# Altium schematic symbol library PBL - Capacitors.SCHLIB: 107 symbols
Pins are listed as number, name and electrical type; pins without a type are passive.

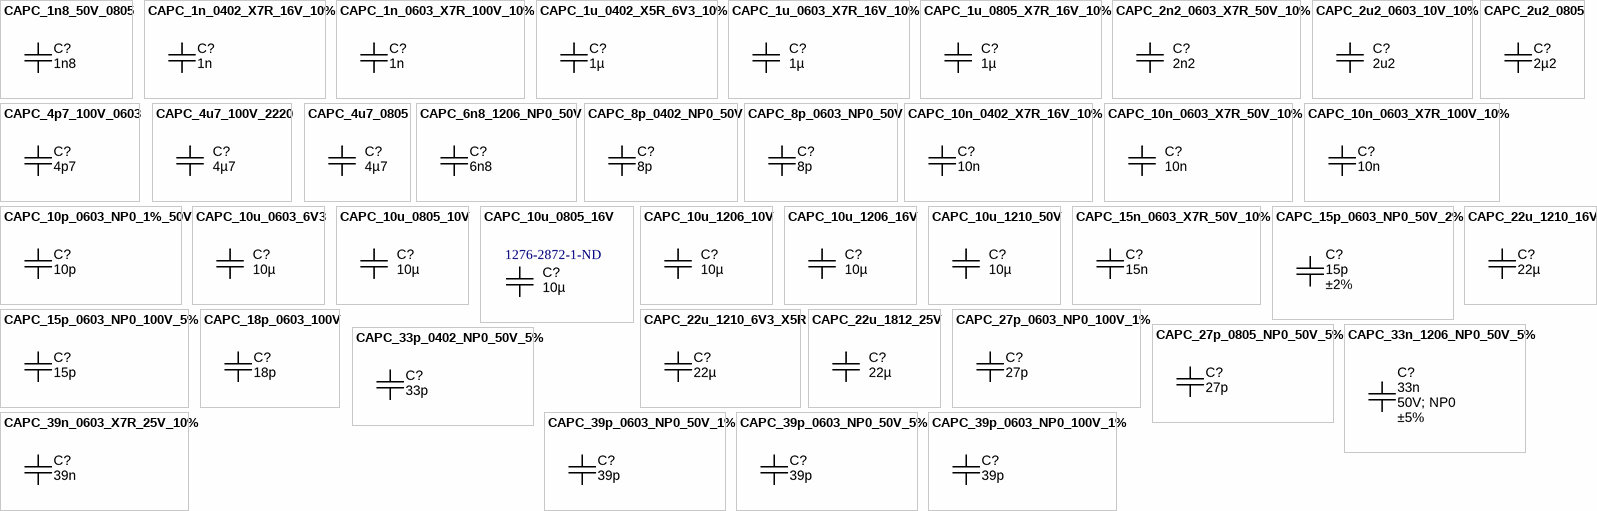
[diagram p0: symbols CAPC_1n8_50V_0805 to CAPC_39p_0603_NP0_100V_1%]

## CAPC_1n8_50V_0805
designator C?, comment value 1n8  (hidden comment: approved sub OK)
Capacitor SMD Cer 1.8nF 10% 50V X7R 0805; Manufacturer 1: AVX Corporation; Manufacturer Part Number 1: 08055C182KAT2A; Ratings: 50V; X7R; SCDType: source*
footprint CAPC2012X135N (Chip Capacitor, Body 2.0x1.2mm, 0805, IPC Medium Density)
pins: 1, 2

## CAPC_1n_0402_X7R_16V_10%
designator C?, comment 1n
Capacitor SMD Cer 1nF 10% 16V X7R 0402; Manufacturer 1: AVX Corporation; Manufacturer Part Number 1: 0402YC102KAT2A; Ratings: 16V; X7R; SCDType: spec
footprint CAPC1005X55N (Chip Capacitor, Body 1.0x0.5mm, 0402, IPC Medium Density)
pins: 1, 2

## CAPC_1n_0603_X7R_100V_10%
designator C?, comment value 1n  (hidden comment: approved sub OK)
Capacitor SMD Cer 1nF 10% 100V X7R 0603; Manufacturer 1: Murata Electronics North America; Manufacturer Part Number 1: GCM188R72A102KA37D; Ratings: 100V; X7R; Material: ceramic; SCDType: spec
footprint CAPC1608X90N (Chip Capacitor, Body 1.6x0.8mm, 0603, IPC Medium Density)
pins: 1, 2

## CAPC_1u_0402_X5R_6V3_10%
designator C?, comment 1µ
Capacitor SMD Cer 1uF 10% 16V X5R 0402; Manufacturer 1: AVX Corporation; Manufacturer Part Number 1: 04026D105KAT2A; Ratings: 6.3V; X5R; SCDType: spec
footprint CAPC1005X55N (Chip Capacitor, Body 1.0x0.5mm, 0402, IPC Medium Density)
pins: 1, 2

## CAPC_1u_0603_X7R_16V_10%
designator C?, comment value 1µ  (hidden comment: approved sub OK)
Capacitor SMD Cer 1uF 10% 16V X7R 0603; Manufacturer 1: TDK Corporation; Manufacturer Part Number 1: C1608X7R1C105K; Ratings: 16V; X7R; Material: ceramic; SCDType: spec
footprint CAPC1608X90N (Chip Capacitor, Body 1.6x0.8mm, 0603, IPC Medium Density)
pins: 1, 2

## CAPC_1u_0805_X7R_16V_10%
designator C?, comment value 1µ  (hidden comment: approved sub OK)
Capacitor SMD Cer 1uF 10% 16V X7R 0805; Manufacturer 1: Yageo; Manufacturer Part Number 1: CC0805KKX7R7BB105; Ratings: 16V; X7R; Material: ceramic; SCDType: spec
footprint CAPC2012X135N (Chip Capacitor, Body 2.0x1.2mm, 0805, IPC Medium Density)
pins: 1, 2

## CAPC_2n2_0603_X7R_50V_10%
designator C?, comment value 2n2  (hidden comment: approved sub OK)
Capacitor SMD Cer 2n2F 10% 50V X7R 0603
footprint CAPC1608X90N (Chip Capacitor, Body 1.6x0.8mm, 0603, IPC Medium Density)
pins: 1, 2

## CAPC_2u2_0603_10V_10%
designator C?, comment value 2u2  (hidden comment: approved sub OK)
Capacitor SMD Cer 2.2uF 10% 10V X5R 0603; Manufacturer 1: AVX Corporation; Manufacturer Part Number 1: 0603ZD225KAT2A; Ratings: 10V; X5R; Material: ceramic; SCDType: spec
footprint CAPC1608X90N (Chip Capacitor, Body 1.6x0.8mm, 0603, IPC Medium Density)
pins: 1, 2

## CAPC_2u2_0805
designator C?, comment value 2µ2  (hidden comment: approved sub OK)
Capacitor SMD Cer 2.2uF 10% 16V X7R 0805; Manufacturer 1: Kemet; Manufacturer Part Number 1: C0805C225K4RACTU; Ratings: 16V; X7R; SCDType: undef
footprint CAPC2012X135N (Chip Capacitor, Body 2.0x1.2mm, 0805, IPC Medium Density)
pins: 1, 2

## CAPC_4p7_100V_0603
designator C?, comment value 4p7  (hidden comment: approved sub OK)
Capacitor SMD Cer 4.7pF ±0.25pF 100V NP0 0603; Manufacturer 1: AVX Corporation; Manufacturer Part Number 1: 06031A4R7CAT2A; Ratings: 100V; NP0; SCDType: source*
footprint CAPC1608X90N (Chip Capacitor, Body 1.6x0.8mm, 0603, IPC Medium Density)
pins: 1, 2

## CAPC_4u7_100V_2220
designator C?, comment value 4µ7  (hidden comment: approved sub OK)
Capacitor SMD Cer 4.7uF 10% 100V X7R 2220; Manufacturer: TDK Corporation; Manufacturer Part Number: C5750X7R2A475K; Ratings: 100V; X7R; Material: ceramic; SCDType: undef
footprint CAPC5750X250N (Chip Capacitor, Body 5.7x5.0mm, 2220, IPC Medium Density)
pins: 1, 2

## CAPC_4u7_0805
designator C?, comment value 4µ7  (hidden comment: approved sub OK)
Capacitor SMD Cer 4.7uF 10% 16V X5R 0805; Manufacturer 1: Taiyo Yuden; Manufacturer Part Number 1: EMK212BJ475KG-T; Ratings: 16V; X5R; Material: ceramic; SCDType: spec
footprint CAPC2012X135N (Chip Capacitor, Body 2.0x1.2mm, 0805, IPC Medium Density)
pins: 1, 2

## CAPC_6n8_1206_NP0_50V
designator C?, comment 6n8
Capacitor SMD Cer 6.8nF 5% 50V NP0 1206; Manufacturer 1: TDK Corporation; Manufacturer Part Number 1: C3216C0G1H682J/0.60; Ratings: 50V; NP0; Material: Ceramic NP0; SCDType: spec
footprint CAPC3216X180N (Chip Capacitor, Body 3.2x1.6mm, 1.8mm H, 1206, IPC Medium Density)
pins: 1, 2

## CAPC_8p_0402_NP0_50V
designator C?, comment 8p
Capacitor SMD Cer 8pF ±0.5pF 50V NP0 0402; Manufacturer 1: Murata Electronics North America; Manufacturer Part Number 1: GRM1555C1H8R0DA01D; Ratings: 50V; NP0; SCDType: spec
footprint CAPC1005X55N (Chip Capacitor, Body 1.0x0.5mm, 0402, IPC Medium Density)
pins: 1, 2

## CAPC_8p_0603_NP0_50V
designator C?, comment 8p
Capacitor SMD Cer 8pF ±0.5pF 50V NP0 0603; Manufacturer 1: Murata Electronics North America; Manufacturer Part Number 1: GRM1885C1H8R0DZ01D; Ratings: 50V; NP0; SCDType: undef
footprint CAPC1608X90N (Chip Capacitor, Body 1.6x0.8mm, 0603, IPC Medium Density)
pins: 1, 2

## CAPC_10n_0402_X7R_16V_10%
designator C?, comment 10n
Capacitor SMD Cer 10nF 10% 16V X7R 0402; Manufacturer 1: AVX Corporation; Manufacturer Part Number 1: 0402YC103KAT2A; Ratings: 16V; X7R; SCDType: spec
footprint CAPC1005X55N (Chip Capacitor, Body 1.0x0.5mm, 0402, IPC Medium Density)
pins: 1, 2

## CAPC_10n_0603_X7R_50V_10%
designator C?, comment value 10n  (hidden comment: approved sub OK)
Capacitor SMD Cer 10nF 10% 50V X7R 0603; Manufacturer 1: TDK Corporation; Manufacturer Part Number 1: C1608X7R1H103K; Ratings: 50V; X7R; Material: ceramic; SCDType: spec
footprint CAPC1608X90N (Chip Capacitor, Body 1.6x0.8mm, 0603, IPC Medium Density)
pins: 1, 2

## CAPC_10n_0603_X7R_100V_10%
designator C?, comment value 10n  (hidden comment: approved sub OK)
Capacitor SMD Cer 10nF 10% 100V X7R 0603; Manufacturer: Murata Electronics North America; Manufacturer Part Number: GCM188R72A103KA37D; Ratings: 100V; X7R; Material: ceramic; SCDType: undef
footprint CAPC1608X90N (Chip Capacitor, Body 1.6x0.8mm, 0603, IPC Medium Density)
pins: 1, 2

## CAPC_10p_0603_NP0_1%_50V
designator C?, comment 10p
Capacitor SMD Cer 10pF 5% 50V NP0 0603; Manufacturer 1: Murata Electronics North America; Manufacturer Part Number 1: GRM1885C1H100FA01J; Ratings: 50V; NP0; SCDType: spec
footprint CAPC1608X90N (Chip Capacitor, Body 1.6x0.8mm, 0603, IPC Medium Density)
pins: 1, 2

## CAPC_10u_0603_6V3
designator C?, comment value 10µ  (hidden comment: approved sub OK)
Capacitor SMD Cer 10uF 10% 10V X5R 0603; Ratings: 10V; X5R; Material: ceramic; SCDType: spec
footprint CAPC1608X90N (Chip Capacitor, Body 1.6x0.8mm, EIA 0603, IPC Medium Density)
pins: 1, 2

## CAPC_10u_0805_10V
designator C?, comment value 10µ  (hidden comment: approved sub OK)
Capacitor SMD Cer 10uF 10% 10V X5R 0805; Manufacturer 1: AVX Corporation; Manufacturer Part Number 1: 0805ZD106KAT2A; Ratings: 10V; X5R; Material: ceramic; SCDType: spec
footprint CAPC2012X135N (Chip Capacitor, Body 2.0x1.2mm, 0805, IPC Medium Density)
pins: 1, 2

## CAPC_10u_0805_16V
designator C?, comment value 10µ  Supplier Part Number 1: 1276-2872-1-ND  (hidden comment: approved sub OK)
Capacitor SMD Cer 10uF 10% 16V X7R 0805; Manufacturer 1: Samsung; Manufacturer Part Number 1: CL21B106KOQNNNE; Ratings: 16V; X7R; Material: ceramic; SCDType: undef
footprint CAPC1608N (Chip Capacitor, Body 1.6x0.8mm, IPC Medium Density)
footprint CAPC3216N (Chip Capacitor, Body 3.2x1.6mm, IPC Medium Density)
footprint CAPC2012X135N (Chip Capacitor, Body 2.0x1.2mm, 0805, IPC Medium Density)
pins: 1, 2

## CAPC_10u_1206_10V
designator C?, comment value 10µ  (hidden comment: approved sub OK)
Capacitor SMD Cer 10uF 10% 10V X5R 1206; Manufacturer 1: KEMET; Manufacturer Part Number 1: C1206C106K8PACTU; Ratings: 10V; X5R; Material: ceramic; SCDType: undef
footprint CAPC3216X180N (Chip Capacitor, Body 3.2x1.6mm, 1.8mm H, 1206, IPC Medium Density)
pins: 1, 2

## CAPC_10u_1206_16V
designator C?, comment value 10µ  (hidden comment: approved sub OK)
Capacitor SMD Cer 10uF 10% 16V X7R 1206; Manufacturer 1: Kemet; Manufacturer Part Number 1: C1206C106K4RACTU; Ratings: 16V; X7R; Material: ceramic; SCDType: spec
footprint CAPC3216X180N (Chip Capacitor, Body 3.2x1.6mm, 1.8mm H, 1206, IPC Medium Density)
pins: 1, 2

## CAPC_10u_1210_50V
designator C?, comment 10µ
Capacitor SMD Cer 10uF 20% 16V X5R 1210; Manufacturer 1: Taiyo Yuden; Manufacturer Part Number 1: UMK325BJ106MM-T; Ratings: 50V; X5R; Material: ceramic; SCDType: spec
footprint CAPC3225X220N (Chip Capacitor, Body 3.2x2.5mm, 1210, IPC Medium Density)
pins: 1, 2

## CAPC_15n_0603_X7R_50V_10%
designator C?, comment value 15n  (hidden comment: approved sub OK)
Capacitor SMD Cer 15nF 10% 50V X7R 0603; Manufacturer Part Number 1: GRM188R71H153KA01D; Manufacturer 1: Murata Electronics North America; Ratings: 50V; X7R; SCDType: spec
footprint CAPC1608X90N (Chip Capacitor, Body 1.6x0.8mm, 0603, IPC Medium Density)
pins: 1, 2

## CAPC_15p_0603_NP0_50V_2%
designator C?, comment Tolerance: ±2%  (hidden comment: 15p)
Capacitor SMD Cer 15pF 2% 50V NP0 0603; Manufacturer 1: TDK Corporation; Manufacturer Part Number 1: C1608C0G1H150G080AA; Ratings: 50V; NP0; SCDType: source
pins: 1, 2

## CAPC_15p_0603_NP0_100V_5%
designator C?, comment 15p
Capacitor SMD Cer 15pF 5% 100V NP0 0603; Manufacturer 1: AVX Corporation; Manufacturer Part Number 1: 06031A150JAT2A; Ratings: 100V; NP0; SCDType: spec
footprint CAPC1608X90N (Chip Capacitor, Body 1.6x0.8mm, 0603, IPC Medium Density)
pins: 1, 2

## CAPC_18p_0603_100V
designator C?, comment 18p
Capacitor SMD Cer 18pF 2% 100V NP0 0603; Manufacturer 1: AVX Corporation; Manufacturer Part Number 1: 06031A180GAT2A; Ratings: 100V; NP0; SCDType: spec
footprint CAPC1608X90N (Chip Capacitor, Body 1.6x0.8mm, 0603, IPC Medium Density)
pins: 1, 2

## CAPC_22u_1210_6V3_X5R
designator C?, comment value 22µ  (hidden comment: approved sub OK)
Capacitor SMD Cer 22uF 20% 6.3V X5R 1210; Manufacturer 1: TDK Corporation; Manufacturer Part Number 1: C3225X5R0J226M/2.00; Ratings: 6.3V; X5R; Voltage - Rated: 6V3; SCDType: spec
footprint CAPC3225X220N (Chip Capacitor, Body 3.2x2.5mm, 1210, IPC Medium Density)
pins: 1, 2

## CAPC_22u_1210_16V
designator C?, comment value 22µ  (hidden comment: approved sub OK)
Capacitor SMD Cer 22uF 20% 16V X7R 1210; Manufacturer: TDK Corporation; Manufacturer Part Number: C3225X7R1C226K; Ratings: 16V; X7R; SCDType: spec
footprint CAPC3225X220N (Chip Capacitor, Body 3.2x2.5mm, 1210, IPC Medium Density)
pins: 1, 2

## CAPC_22u_1812_25V
designator C?, comment value 22µ  (hidden comment: approved sub OK)
Capacitor SMD Cer 22uF 20% 25V X5R 1812; Manufacturer 1: TDK Corporation; Manufacturer Part Number 1: C4532X5R1E226M; Ratings: 25V; X5R; Material: ceramic; SCDType: undef
footprint CAPC4532X280N (Chip Capacitor, Body 4.5x3.2mm, 1812, IPC Medium Density)
pins: 1, 2

## CAPC_27p_0603_NP0_100V_1%
designator C?, comment 27p
Capacitor SMD Cer 27pF 1% 100V NP0 0603; Manufacturer 1: AVX Corporation; Manufacturer Part Number 1: 06031A270FAT2A; Ratings: 100V; NP0; SCDType: undef
footprint CAPC1608X90N (Chip Capacitor, Body 1.6x0.8mm, 0603, IPC Medium Density)
pins: 1, 2

## CAPC_27p_0805_NP0_50V_5%
designator C?, comment value 27p  (hidden comment: approved sub OK)
Capacitor SMD Cer 27pF 5% 50V NP0 0805; Manufacturer 1: Panasonic - ECG; Manufacturer Part Number 1: ECJ-2VC1H270J; Ratings: 50V; NP0; SCDType: undef
footprint CAPC2012X135N (Chip Capacitor, Body 2.0x1.2mm, 0805, IPC Medium Density)
pins: 1, 2

## CAPC_33n_1206_NP0_50V_5%
designator C?, comment Tolerance: ±5%  Ratings: 50V; NP0  (hidden comment: 33n)
Capacitor SMD Cer 33nF 1206 NP0 50V 5%; Manufacturer 1: TDK Corporation; Manufacturer Part Number 1: C3216C0G1H333J085AA; SCDType: undef
footprint CAPC3216X100N (Chip Capacitor, Body 3.2x1.6mm, 1.0mm H, 1206, IPC Medium Density)
pins: 1, 2

## CAPC_33p_0402_NP0_50V_5%
designator C?, comment 33p
Capacitor SMD Cer 33pF 5% 50V NP0 0402; Manufacturer 1: AVX Corporation; Manufacturer Part Number 1: 04025A330JAT2A; Ratings: 50V; NP0; SCDType: spec
footprint CAPC1005X55N (Chip Capacitor, Body 1.0x0.5mm, 0402, IPC Medium Density)
pins: 1, 2

## CAPC_39n_0603_X7R_25V_10%
designator C?, comment value 39n  (hidden comment: approved sub OK)
Capacitor SMD Cer 39nF 10% 25V X7R 0603; Manufacturer 1: Kemet; Manufacturer Part Number 1: C0603C393K3RACTU; Ratings: 100V; X7R; Material: ceramic; SCDType: spec
footprint CAPC1608X90N (Chip Capacitor, Body 1.6x0.8mm, 0603, IPC Medium Density)
pins: 1, 2

## CAPC_39p_0603_NP0_50V_1%
designator C?, comment 39p
Capacitor SMD Cer 39pF 1% 50V NP0 0603; Manufacturer 1: AVX Corporation; Manufacturer Part Number 1: 06035A390FAT; Ratings: 50V; NP0; SCDType: source; Temperature Coefficient: C0G, NP0
footprint CAPC1608X90N (Chip Capacitor, Body 1.6x0.8mm, 0603, IPC Medium Density)
pins: 1, 2

## CAPC_39p_0603_NP0_50V_5%
designator C?, comment 39p
Capacitor SMD Cer 39pF 5% 50V NP0 0603; Manufacturer 1: TDK Corporation; Manufacturer Part Number 1: C1608C0G1H390J; Ratings: 50V; NP0; SCDType: undef
footprint CAPC1608X90N (Chip Capacitor, Body 1.6x0.8mm, 0603, IPC Medium Density)
pins: 1, 2

## CAPC_39p_0603_NP0_100V_1%
designator C?, comment 39p
Capacitor SMD Cer 39pF 1% 100V NP0 0603; Manufacturer 1: AVX Corporation; Manufacturer Part Number 1: 06031A390FAT2A; Ratings: 100V; NP0; SCDType: source; Temperature Coefficient: C0G, NP0
footprint CAPC1608X90N (Chip Capacitor, Body 1.6x0.8mm, 0603, IPC Medium Density)
pins: 1, 2

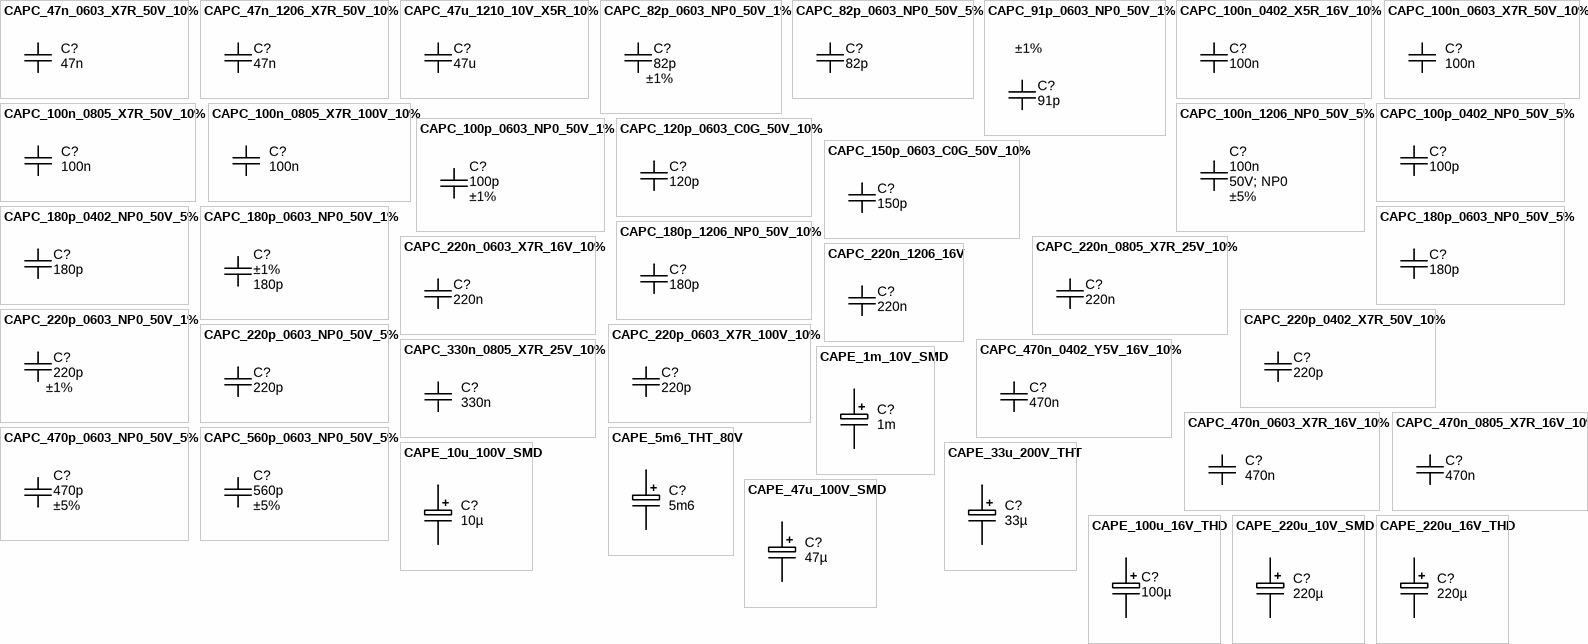
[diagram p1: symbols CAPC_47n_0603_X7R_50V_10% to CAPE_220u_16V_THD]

## CAPC_47n_0603_X7R_50V_10%
designator C?, comment 47n
Capacitor SMD Cer 47nF 10% 50V X7R 0603; Manufacturer 1: AVX Corporation; Manufacturer Part Number 1: 06035C473KAT2A; Ratings: 50V; X7R; Material: ceramic; SCDType: spec
footprint CAPC1608X90N (Chip Capacitor, Body 1.6x0.8mm, 0603, IPC Medium Density)
footprint CAPC3216N (Chip Capacitor, Body 3.2x1.6mm, IPC Medium Density)
footprint CAPC2012N (Chip Capacitor, Body 2.0x1.2mm, IPC Medium Density)
pins: 1, 2

## CAPC_47n_1206_X7R_50V_10%
designator C?, comment 47n
Capacitor SMD Cer 47nF 10% 50V X7R 1206; Manufacturer 1: Yageo; Manufacturer Part Number 1: CC1206KRX7R9BB473; Ratings: 50V; X7R; SCDType: spec
footprint CAPC3216X180N (Chip Capacitor, Body 3.2x1.6mm, 1.8mm H, 1206, IPC Medium Density)
pins: 1, 2

## CAPC_47u_1210_10V_X5R_10%
designator C?, comment 47u
Capacitor SMD Cer 47uF 10% 10V 1210; Manufacturer 1: Murata Electronics North America; Manufacturer Part Number 1: GRM32ER61A476KE20L; Ratings: 10V; X5R; SCDType: undef
footprint CAPC3225X220N (Chip Capacitor, Body 3.2x2.5mm, 1210, IPC Medium Density)
pins: 1, 2

## CAPC_82p_0603_NP0_50V_1%
designator C?, comment Tolerance: ±1%  (hidden comment: 82p)
Capacitor SMD Cer 82pF 1% 50V NP0 0603; Manufacturer 1: Kemet; Manufacturer Part Number 1: C0603C820F5GACTU; Ratings: 50V; NP0; SCDType: spec
footprint CAPC1608X90N (Chip Capacitor, Body 1.6x0.8mm, 0603, IPC Medium Density)
pins: 1, 2

## CAPC_82p_0603_NP0_50V_5%
designator C?, comment 82p
Capacitor SMD Cer 82pF 5% 50V NP0 0603; Manufacturer 1: Yageo; Manufacturer Part Number 1: CC0603JRNPO9BN820; Ratings: 50V; NP0; SCDType: undef
footprint CAPC1608X90N (Chip Capacitor, Body 1.6x0.8mm, 0603, IPC Medium Density)
pins: 1, 2

## CAPC_91p_0603_NP0_50V_1%
designator C?, comment Tolerance: ±1%  (hidden comment: 91p)
Capacitor SMD Cer 91pF 1% 50V NP0 0603; Manufacturer 1: AVX Corporation; Manufacturer Part Number 1: 06035U910FAT2A; Ratings: 50V; NP0; SCDType: source
footprint CAPC1608X90N (Chip Capacitor, Body 1.6x0.8mm, 0603, IPC Medium Density)
pins: 1, 2

## CAPC_100n_0402_X5R_16V_10%
designator C?, comment 100n
Capacitor SMD Cer 100nF 10% 16V X5R 0402; Manufacturer 1: AVX Corporation; Manufacturer Part Number 1: 0402YD104KAT2A; Ratings: 16V; X5R; SCDType: spec
footprint CAPC1005X55N (Chip Capacitor, Body 1.0x0.5mm, 0402, IPC Medium Density)
pins: 1, 2

## CAPC_100n_0603_X7R_50V_10%
designator C?, comment value 100n  (hidden comment: approved sub OK)
Capacitor SMD Cer 100nF 10% 50V X7R 0603; Manufacturer 1: AVX Corporation; Manufacturer Part Number 1: 06035C104KAT2A; Ratings: 50V; X7R; Material: ceramic; SCDType: spec
footprint CAPC1608X90N (Chip Capacitor, Body 1.6x0.8mm, 0603, IPC Medium Density)
pins: 1, 2

## CAPC_100n_0805_X7R_50V_10%
designator C?, comment value 100n  (hidden comment: approved sub OK)
Capacitor SMD Cer 100nF 10% 50V X7R 0805; Manufacturer 1: Kemet; Manufacturer Part Number 1: C0805C104K5RACTU; Ratings: 50V; X7R; Material: ceramic; SCDType: undef
footprint CAPC1608N (Chip Capacitor, Body 1.6x0.8mm, IPC Medium Density)
footprint CAPC3216N (Chip Capacitor, Body 3.2x1.6mm, IPC Medium Density)
footprint CAPC2012X135N (Chip Capacitor, Body 2.0x1.2mm, 0805, IPC Medium Density)
pins: 1, 2

## CAPC_100n_0805_X7R_100V_10%
designator C?, comment value 100n  (hidden comment: approved sub OK)
Capacitor SMD Cer 100nF 10% 100V X7R 0805; Manufacturer 1: TDK Corporation; Manufacturer Part Number 1: C2012X7R2A104K; Ratings: 100V; X7R; Material: ceramic; SCDType: undef
footprint CAPC2012X135N (Chip Capacitor, Body 2.0x1.2mm, 0805, IPC Medium Density)
pins: 1, 2

## CAPC_100n_1206_NP0_50V_5%
designator C?, comment Tolerance: ±5%  Ratings: 50V; NP0  (hidden comment: 100n)
Capacitor SMD Cer 100nF 1206 NP0 50V 5%; Manufacturer 1: TDK Corporation; Manufacturer Part Number 1: C3216C0G1H104J160AA; SCDType: undef
footprint CAPC3216X180N (Chip Capacitor, Body 3.2x1.6mm, 1.8mm H, 1206, IPC Medium Density)
pins: 1, 2

## CAPC_100p_0402_NP0_50V_5%
designator C?, comment 100p
Capacitor SMD Cer 100pF 5% 50V NP0 0402; Manufacturer 1: Yageo; Manufacturer Part Number 1: CC0402JRNPO9BN101; Ratings: 50V; NP0; SCDType: spec
footprint CAPC1005X55N (Chip Capacitor, Body 1.0x0.5mm, 0402, IPC Medium Density)
pins: 1, 2

## CAPC_100p_0603_NP0_50V_1%
designator C?, comment Tolerance: ±1%  (hidden comment: 100p)
Capacitor SMD Cer 100pF 1% 50V NP0 0603; Manufacturer 1: AVX Corporation; Manufacturer Part Number 1: 06035A101FAT2A; Ratings: 50V; NP0; SCDType: source
footprint CAPC1608X90N (Chip Capacitor, Body 1.6x0.8mm, 0603, IPC Medium Density)
pins: 1, 2

## CAPC_120p_0603_C0G_50V_10%
designator C?, comment 120p
Capacitor SMD Cer 120pF 10% 50V NP0 0603; Manufacturer 1: Kemet; Manufacturer Part Number 1: C0603C121K5GACTU; Ratings: 50V; NP0; SCDType: spec
footprint CAPC1608X90N (Chip Capacitor, Body 1.6x0.8mm, 0603, IPC Medium Density)
pins: 1, 2

## CAPC_150p_0603_C0G_50V_10%
designator C?, comment 150p
Capacitor SMD Cer 150pF 10% 50V C0G 0603; Manufacturer 1: Kemet; Manufacturer Part Number 1: C0603C151K5GACTU; Ratings: 50V; C0G; SCDType: spec
footprint CAPC1608X90N (Chip Capacitor, Body 1.6x0.8mm, 0603, IPC Medium Density)
pins: 1, 2

## CAPC_180p_0402_NP0_50V_5%
designator C?, comment 180p
Capacitor SMD Cer 180pF 5% 50V NP0 0402; Manufacturer 1: AVX Corporation; Manufacturer Part Number 1: 04025A181JAT2A; Ratings: 50V; NP0; SCDType: spec
footprint CAPC1005X55N (Chip Capacitor, Body 1.0x0.5mm, 0402, IPC Medium Density)
pins: 1, 2

## CAPC_180p_0603_NP0_50V_1%
designator C?, comment Tolerance: ±1%  (hidden comment: 180p)
Capacitor SMD Cer 180pF 1% 50V NP0 0603; Manufacturer 1: AVX Corporation; Manufacturer Part Number 1: 06035A181FAT2A; Ratings: 50V; NP0; SCDType: source
footprint CAPC1608X90N (Chip Capacitor, Body 1.6x0.8mm, 0603, IPC Medium Density)
pins: 1, 2

## CAPC_180p_0603_NP0_50V_5%
designator C?, comment 180p
Capacitor SMD Cer 180pF 5% 50V NP0 0603; Manufacturer 1: Yageo; Manufacturer Part Number 1: CC0603JRNPO9BN181; Ratings: 50V; C0G; SCDType: undef
footprint CAPC1608X90N (Chip Capacitor, Body 1.6x0.8mm, 0603, IPC Medium Density)
pins: 1, 2

## CAPC_180p_1206_NP0_50V_10%
designator C?, comment 180p
Capacitor SMD Cer 180pF 10% 50V NP0 1206; Manufacturer 1: Kemet; Manufacturer Part Number 1: C1206C181K5GACTU; Ratings: 50V; NP0; SCDType: spec
footprint CAPC3216X180N (Chip Capacitor, Body 3.2x1.6mm, 1.8mm H, 1206, IPC Medium Density)
pins: 1, 2

## CAPC_220n_0603_X7R_16V_10%
designator C?, comment value 220n  (hidden comment: approved sub OK)
Capacitor SMD Cer 220nF 10% 16V X7R 0603; Manufacturer 1: TDK Corporation; Manufacturer Part Number 1: C1608X7R1C224K; Ratings: 16V; X7R; SCDType: undef
footprint CAPC1608X90N (Chip Capacitor, Body 1.6x0.8mm, 0603, IPC Medium Density)
pins: 1, 2

## CAPC_220n_0805_X7R_25V_10%
designator C?, comment value 220n  (hidden comment: approved sub OK)
Capacitor SMD Cer 220nF 10% 25V X7R 0805; Manufacturer 1: Murata Electronics North America; Manufacturer Part Number 1: GRM219R71E224KA01D; Ratings: 25V; X7R; SCDType: undef
footprint CAPC2012X135N (Chip Capacitor, Body 2.0x1.2mm, 0805, IPC Medium Density)
pins: 1, 2

## CAPC_220n_1206_16V
designator C?, comment value 220n  (hidden comment: approved sub OK)
Capacitor SMD Cer 220nF 10% 16V X7R 1206; Manufacturer 1: Murata; Manufacturer Part Number 1: GRM319R71C224KA01D; Ratings: 16V; X7R; SCDType: spec
footprint CAPC3216X180N (Chip Capacitor, Body 3.2x1.6mm, 1.8mm H, 1206, IPC Medium Density)
pins: 1, 2

## CAPC_220p_0402_X7R_50V_10%
designator C?, comment value 220p  (hidden comment: approved sub OK)
Capacitor SMD Cer 220pF 10% 0402 X7R 50V; Manufacturer 1: TDK Corporation; Manufacturer Part Number 1: C1005X7R1H221K050BA; Ratings: 50V; X7R; SCDType: undef
footprint CAPC1005X55N (Chip Capacitor, Body 1.0x0.5mm, 0402, IPC Medium Density)
pins: 1, 2

## CAPC_220p_0603_NP0_50V_1%
designator C?, comment Tolerance: ±1%  (hidden comment: 220p)
Capacitor SMD Cer 220pF 1% 50V NP0 0603; Manufacturer 1: AVX Corporation; Manufacturer Part Number 1: 06035A221FAT2A; Ratings: 50V; NP0; SCDType: spec
footprint CAPC1608X90N (Chip Capacitor, Body 1.6x0.8mm, 0603, IPC Medium Density)
pins: 1, 2

## CAPC_220p_0603_NP0_50V_5%
designator C?, comment 220p
Capacitor SMD Cer 220pF 5% 50V NP0 0603; Manufacturer 1: Murata Electronics North America; Manufacturer Part Number 1: GRM1885C1H221JA01D; Ratings: 50V; NP0; Material: Ceramic NP0; SCDType: spec
footprint CAPC1608X90N (Chip Capacitor, Body 1.6x0.8mm, 0603, IPC Medium Density)
pins: 1, 2

## CAPC_220p_0603_X7R_100V_10%
designator C?, comment value 220p  (hidden comment: approved sub OK)
Capacitor SMD Cer 220pF 10% 0603 X7R 100V; Manufacturer 1: AVX Corporation; Manufacturer Part Number 1: 06031C221KAT2A; Ratings: 100V; X7R; SCDType: undef
footprint CAPC1608X90N (Chip Capacitor, Body 1.6x0.8mm, 0603, IPC Medium Density)
pins: 1, 2

## CAPC_330n_0805_X7R_25V_10%
designator C?, comment value 330n  (hidden comment: approved sub OK)
Capacitor SMD Cer 330nF 10% 25V X7R 0805; Manufacturer 1: Kemet; Manufacturer Part Number 1: C0805C334K3RACTU; Ratings: 25V; X7R; Material: ceramic; SCDType: spec
footprint CAPC2012X135N (Chip Capacitor, Body 2.0x1.2mm, 0805, IPC Medium Density)
pins: 1, 2

## CAPC_470n_0402_Y5V_16V_10%
designator C?, comment 470n
Capacitor SMD Cer 470nF -20% +80% 16V Y5V 0402; Manufacturer 1: Murata Electronics North America; Manufacturer Part Number 1: GRM155F51C474ZA01D; Tolerance: ±10%; Ratings: 16V; Y5V; SCDType: spec
footprint CAPC1005X55N (Chip Capacitor, Body 1.0x0.5mm, 0402, IPC Medium Density)
pins: 1, 2

## CAPC_470n_0603_X7R_16V_10%
designator C?, comment 470n
Capacitor SMD Cer 470nF 10% 16V X7R 0603; Manufacturer 1: Murata Electronics North America; Manufacturer Part Number 1: GRM188R71C474KA88D; Ratings: 16V; X7R; Material: ceramic; SCDType: spec
footprint CAPC1608X90N (Chip Capacitor, Body 1.6x0.8mm, 0603, IPC Medium Density)
pins: 1, 2

## CAPC_470n_0805_X7R_16V_10%
designator C?, comment value 470n  (hidden comment: approved sub OK)
Capacitor SMD Cer 470nF 10% 16V X7R 0805; Manufacturer 1: AVX Corporation; Manufacturer Part Number 1: 0805YC474KAT2A; Ratings: 16V; X7R; SCDType: undef
footprint CAPC2012X135N (Chip Capacitor, Body 2.0x1.2mm, 0805, IPC Medium Density)
pins: 1, 2

## CAPC_470p_0603_NP0_50V_5%
designator C?, comment value 470p  Tolerance: ±5%  (hidden comment: approved sub OK)
Capacitor SMD Cer 470pF 5% 50V NP0 0603; Manufacturer 1: AVX Corporation; Manufacturer Part Number 1: 06035A471JAT2A; Ratings: 50V; NP0; Material: ceramic; SCDType: spec
footprint CAPC1608X90N (Chip Capacitor, Body 1.6x0.8mm, 0603, IPC Medium Density)
pins: 1, 2

## CAPC_560p_0603_NP0_50V_5%
designator C?, comment value 560p  Tolerance: ±5%  (hidden comment: approved sub OK)
Capacitor SMD Cer 560pF 5% 50V NP0 0603; Manufacturer 1: AVX Corporation; Manufacturer Part Number 1: 06035A561JAT2A; Ratings: 50V; NP0; Material: ceramic; Capacitance: 470pF; SCDType: spec
footprint CAPC1608X90N (Chip Capacitor, Body 1.6x0.8mm, 0603, IPC Medium Density)
pins: 1, 2

## CAPE_1m_10V_SMD
designator C?, comment 1m
Capacitor SMD Alum Elec 1mF 20% 10V; Manufacturer 1: Panasonic - ECG; Manufacturer Part Number 1: EEE-FK1A102P; Ratings: 10V; 105°C; Material: Al; Impedance: 80 mOhm; SCDType: spec
footprint CAP_ELEC_Size G (Capacitor, polarized, aluminum can; 10.0x10.2mm DxH)
pins: 1, 2

## CAPE_5m6_THT_80V
designator C?, comment 5m6
Capacitor THT Electrolytic 5600uF 20% 80V; Manufacturer 1: Panasonic - ECG; Manufacturer Part Number 1: ECO-S1KP562DA; Material: Aluminum Electrolytic; SCDType: undef
footprint CAPE10.0MM_Rad_30x45mm (Footprint not found)
pins: 1, 2

## CAPE_10u_100V_SMD
designator C?, comment 10µ
Capacitor SMD Electrolytic 10uF 20% 100V Radial; Manufacturer: Panasonic - ECG; Manufacturer Part Number: EEE-2AA100UP; Material: Aluminum Electrolytic; SCDType: spec
footprint CAP_ELEC_Size E (Capacitor, polarized, aluminum can; 8.0x6.2mm DxH)
pins: 1, 2

## CAPE_33u_200V_THT
designator C?, comment 33µ
Capacitor THT Alum Elec 33uF 20% 200V; Manufacturer 1: Panasonic - ECG; Manufacturer Part Number 1: EEU-ED2D330; Ratings: 200V; 105°C; Material: Al; SCDType: undef
footprint CAPE5.0mm
pins: 1, 2

## CAPE_47u_100V_SMD
designator C?, comment 47µ
Capacitor SMD Electrolytic 47uF 20% 100V Radial; Manufacturer 1: Panasonic - ECG; Manufacturer Part Number 1: EEV-TG2A470Q; Material: Aluminum Electrolytic; SCDType: undef
footprint CAP_ELEC_Size H13 (Capacitor, polarized, aluminum can; 12.5x13.5mm DxH)
pins: 1, 2

## CAPE_100u_16V_THD
designator C?, comment 100µ
Capacitor THD Electrolytic 100uF 20% 16V Radial; Manufacturer: Panasonic - ECG; Manufacturer Part Number: ECA-1CM101; Material: Aluminum Electrolytic; SCDType: spec
footprint CAPAE200P550X1200_FLAT2
pins: 1, 2

## CAPE_220u_10V_SMD
designator C?, comment 220µ
Capacitor SMD Alum Elec 220uF 20% 10V; Manufacturer 1: Panasonic - ECG; Manufacturer Part Number 1: EEE-FK1A221P; Ratings: 10V; 105°C; Material: Al; SCDType: undef
footprint CAP_ELEC_Size E (Capacitor, polarized, aluminum can; 6.20mm L X 8mm D)
pins: 1, 2

## CAPE_220u_16V_THD
designator C?, comment 220µ
Capacitor THT Alum Elec 220uF 20% 16V; Manufacturer 1: Nichicon; Manufacturer Part Number 1: UPW1C221MPD; Ratings: 16V; 80°C; Material: Al; SCDType: undef
footprint CAPE3.5mm
pins: 1, 2

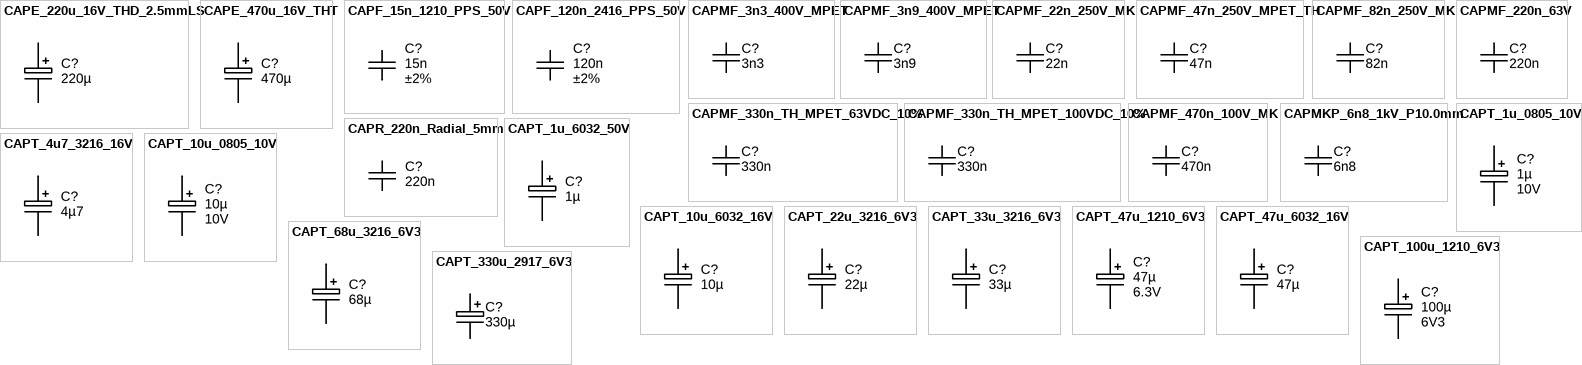
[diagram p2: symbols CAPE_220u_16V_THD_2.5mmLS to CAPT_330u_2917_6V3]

## CAPE_220u_16V_THD_2.5mmLS
designator C?, comment 220µ
Capacitor THT Alum Elec 220uF 20% 16V 2.5mmLS; Manufacturer 1: Nichicon; Manufacturer Part Number 1: UVR1C221MED; Ratings: 16V; 80°C; Material: Al; SCDType: undef
footprint CAPE2.5mm_max6.8x12.5mm
pins: 1, 2

## CAPE_470u_16V_THT
designator C?, comment 470µ
Capacitor THT Alum Elec 470uF 20% 16V; Manufacturer 1: NICHICON; Manufacturer Part Number 1: UHM1C471MPD6; Ratings: 16V; 105°C; Material: Al Electrolytic; SCDType: undef
footprint CAPE10.0MM_Rad_10x14mm (10mm Pitch Radial Capacitor 10x14mm DxH)
pins: 1, 2

## CAPF_15n_1210_PPS_50V
designator C?, comment value 15n  Tolerance: ±2%  (hidden comment: Polyphenylene Sulphide (PPS))
Capacitor SMD PPS Film 15nF 2% 50V 1210; Manufacturer 1: Panasonic - ECG; Manufacturer Part Number 1: ECH-U1H153GX5; Ratings: 50 V; PPS Film; SCDType: spec
footprint CAPC3225X220N (Chip Capacitor, Body 3.2x2.5mm, 1210, IPC Medium Density)
pins: 1, 2

## CAPF_120n_2416_PPS_50V
designator C?, comment value 120n  Tolerance: ±2%  (hidden comment: Polyphenylene Sulphide (PPS))
Capacitor SMD PPS Film 120nF 2% 50V 2416; Manufacturer 1: Panasonic - ECG; Manufacturer Part Number 1: ECH-U1H124GX9; Ratings: 50 V; PPS Film; SCDType: spec
footprint CAPC6041X210N (Stacked film capacitor, Body 6.0x4.1mm, 2416, IPC Nominal settings)
pins: 1, 2

## CAPMF_3n3_400V_MPET
designator C?, comment 3n3
Capacitor THD Metallized PET Film 3.3nF 10% 400V; Manufacturer 1: Wing Fu Technology; Manufacturer Part Number 1: CL21-332-K-400V-7.5; Material: Metallized Polyester; SCDType: spec
footprint CAPMF5.0-7.5mm_SL (Capacitor, THT, Metallized Polyester Film)
pins: 1, 2

## CAPMF_3n9_400V_MPET
designator C?, comment 3n9
Capacitor THD Metallized PET Film 3.9nF 10% 400V; Manufacturer 1: Wing Fu Technology; Manufacturer Part Number 1: CL21-392-K-400V-7.5; Material: Metallized Polyester; SCDType: spec
footprint CAPMF5.0-7.5mm_SL (Capacitor, THT, Metallized Polyester Film)
pins: 1, 2

## CAPMF_22n_250V_MK
designator C?, comment 22n
Capacitor THD MK Film 22nF 10% 250V; Manufacturer 1: Panasonic - ECG; Manufacturer Part Number 1: ECQ-E2223KF; Material: Metallized Polyester; SCDType: undef
footprint CAPMF12.5x4.5x9.0x10mmLS (Capacitor, MF, Thru-Hole, Dipped Radial; Body 12.5 x 4.5 x 9.0 mm (WxTxH) Pin Spacing 10.0 mm (typ))
pins: 1, 2

## CAPMF_47n_250V_MPET_TH
designator C?, comment 47n
Capacitor THD Metallized PET Film 47nF 5% 250V; Manufacturer 1: EPCOS Inc; Manufacturer Part Number 1: B32529C3473J; Ratings: 250VDC; 160VAC; Material: Metallized Polyester; Dielectric Material: Polyester, Metallized; SCDType: source
footprint CAPM50P720350X800_FLAT (Capacitor, THT, Metallized Polyester Film with 7.2x3.5x8.0mm LxTxH)
pins: 1, 2

## CAPMF_82n_250V_MK
designator C?, comment 82n
Capacitor THD MK Film 82nF 10% 250V; Manufacturer 1: Panasonic - ECG; Manufacturer Part Number 1: ECQ-E2823KF; Material: Metallized Polyester; SCDType: undef
footprint CAPMF12.5x4.5x9.0x10mmLS (Capacitor, MF, Thru-Hole, Dipped Radial; Body 12.5 x 4.5 x 9.0 mm (WxTxH) Pin Spacing 10.0 mm (typ))
pins: 1, 2

## CAPMF_220n_63V
designator C?, comment 220n
Capacitor, THT, metallized polyester; Manufacturer 1: SunTan; Manufacturer Part Number 1: TS03-224J-63V-7.5; Tolerance: ±5%; Ratings: 63V; Material: Metallized Polyester; Epoxy Resin; SCDType: undef
footprint CAPMF7.5mm (Capacitor, THT, Metallized Polyester Film)
pins: 1, 2

## CAPMF_330n_TH_MPET_63VDC_10%
designator C?, comment 330n
Capacitor THD Metallized PET Film 330nF 10% 63VDC; Manufacturer 1: EPCOS Inc; Manufacturer Part Number 1: B32529C334K; Ratings: 63VDC; 40VAC; Material: Metallized Polyester; SCDType: source
footprint CAPM50P720300X650_FLAT (Capacitor, THT, Metallized Polyester Film with 7.2x3.0x6.5mm LxTxH)
footprint CAPM50P720300X650_VERT (Capacitor, THT, Metallized Polyester Film with 7.2x3.0x6.5mm LxTxH)
pins: 1, 2

## CAPMF_330n_TH_MPET_100VDC_10%
designator C?, comment 330n
Capacitor THD Metallized PET Film 330nF 10% 100VDC; Manufacturer 1: EPCOS Inc; Manufacturer Part Number 1: B32529C1334J; Ratings: 100VDC; 63VAC; Material: Metallized Polyester; SCDType: undef
footprint CAPM50P720350X800_FLAT (Capacitor, THT, Metallized Polyester Film with 7.2x3.5x8.0mm LxTxH)
pins: 1, 2

## CAPMF_470n_100V_MK
designator C?, comment 470n
Capacitor THD MK Film 470nF 10% 100V; Manufacturer 1: Panasonic - ECG; Manufacturer Part Number 1: ECQ-E1474KF; Material: Metallized Polyester; SCDType: undef
footprint CAPR7.62-6.8x2.5 (Capacitor, MF, Thru-Hole, Dipped Radial; Body 6.8 x 2.5 mm (WxT) Pin Spacing 7.62 mm (typ))
pins: 1, 2

## CAPMKP_6n8_1kV_P10.0mm
designator C?, comment 6n8
Capacitor THT metallized polypropylene 6.8nF 5% 1kV 10.0mm pitch; Manufacturer 1: EPCOS Inc; Manufacturer Part Number 1: B32671L0682J000; Material: Metallized Polypropylene Film; SCDType: source/
footprint CAPMF13.0x5.0x11.0x10.0mm LxWxHxP (Capacitor, THT, Metallized Polypropylene Film, 10mm lead pitch)
pins: 1, 2

## CAPR_220n_Radial_5mm
designator C?, comment value 220n  (hidden comment: approved sub OK)
Capacitor Ceramic 220nF 10% 50V X7R radial 5mm lead spacing; Manufacturer 1: TDK Corporation; Manufacturer Part Number 1: FK24X7R1H224K; Ratings: 50V; X7R; SCDType: spec
footprint CAPC500P450250X550 (TDK FK24 radial ceramic capacitor)
pins: 1, 2

## CAPT_1u_0805_10V
designator C?, comment Ratings: 10V  (hidden comment: 1µ)
Capacitor SMD Tantalum 1uF 20% 10V 0805; Manufacturer 1: AVX Corporation; Manufacturer Part Number 1: TAJP106M010RNJ; Manufacturer Size Code: P; ESR (Equivalent Series Resistance): 6.000 Ohm; Type: Molded; SCDType: spec
footprint CAPMP2012X150USR (Molded body capacitor, Body 2.0x1.2mm, 0805, IPC Medium Density)
pins: 1, 2

## CAPT_1u_6032_50V
designator C?, comment 1µ
Capacitor SMD Tantalum 1uF 10% 50V EIA 6032-28; Manufacturer: Vishay/Sprague; Manufacturer Part Number: 293D105X9050C2TE3; SCDType: undef
footprint CAPMP6032X280N (Capacitor, polarized, Molded Body, EIA 535BAAC size C; 6.00mm L X 3.20mm W X 2.80mm H)
pins: 1, 2

## CAPT_4u7_3216_16V
designator C?, comment 4µ7
Capacitor SMD Tantalum 4.7uF 10% 16V 3216-18; Manufacturer 1: Vishay/Sprague; Manufacturer Part Number 1: 293D475X9016A2TE3; SCDType: undef
footprint CAPMP3216X180N (Capacitor, polarized, Molded Body, EIA 535BAAC size A; 3.20mm L X 1.60mm W X 1.80mm H)
pins: 1, 2

## CAPT_10u_0805_10V
designator C?, comment Ratings: 10V  (hidden comment: 10µ)
Capacitor SMD Tantalum 10uF 20% 10V 0805; Manufacturer 1: AVX Corporation; Manufacturer Part Number 1: TAJP106M010RNJ; SCDType: spec
footprint CAPMP2012X150USR (Molded body capacitor, Body 2.0x1.2mm, 0805, IPC Medium Density)
pins: 1, 2

## CAPT_10u_6032_16V
designator C?, comment 10µ
Capacitor SMD Tantalum 10uF 20% 16V EIA 6032-28; Manufacturer 1: Vishay/Sprague; Manufacturer Part Number 1: 293D106X0016C2TE3; SCDType: undef
footprint CAPMP6032X280N (Capacitor, polarized, Molded Body, EIA 535BAAC size C; 6.00mm L X 3.20mm W X 2.80mm H)
pins: 1, 2

## CAPT_22u_3216_6V3
designator C?, comment 22µ
Capacitor SMD Tantalum 22uF 10% 6.3V 3216-18; Manufacturer 1: Kemet; Manufacturer Part Number 1: T491A226K006AT; Material: Solid Tantalum; SCDType: source
footprint CAPMP3216X180N (Capacitor, polarized, Molded Body, EIA 535BAAC size A; 3.20mm L X 1.60mm W X 1.80mm H)
pins: 1, 2

## CAPT_33u_3216_6V3
designator C?, comment 33µ
Capacitor SMD Tantalum 33uF 10% 6.3V 3216-18; Manufacturer 1: Kemet; Manufacturer Part Number 1: T491A336K006AT; Material: Solid Tantalum; SCDType: source
footprint CAPMP3216X180N (Capacitor, polarized, Molded Body, EIA 535BAAC size A; 3.20mm L X 1.60mm W X 1.80mm H)
pins: 1, 2

## CAPT_47u_1210_6V3
designator C?, comment Ratings: 6.3V  (hidden comment: 47µ)
Capacitor SMD Tantalum 47uF 20% 6.3V 1210; Manufacturer 1: AVX Corporation; Manufacturer Part Number 1: TCJB476M006R0070; Manufacturer Size Code: B; Voltage - Rated: 6V3; ESR (Equivalent Series Resistance): 70.0 mOhm; Type: Molded; SCDType: spec
footprint CAPMP3528X210N (Molded body capacitor, Body 3.5x2.8mm, 1210, IPC Nominal settings)
pins: 1, 2

## CAPT_47u_6032_16V
designator C?, comment 47µ
Capacitor SMD Tantalum 47uF 10% 16V 6032-28; Manufacturer 1: Vishay/Sprague; Manufacturer Part Number 1: TR3C476K016C0300; SCDType: undef
footprint CAPMP6032X280N (Capacitor, polarized, Molded Body, EIA 535BAAC size C; 6.00mm L X 3.20mm W X 2.80mm H)
pins: 1, 2

## CAPT_68u_3216_6V3
designator C?, comment 68µ
Capacitor SMD Tantalum 68uF 10% 6.3V EIA 3216-18; Manufacturer 1: Kemet; Manufacturer Part Number 1: T491A686K006AT; Manufacturer Size Code: A; Material: Solid Tantalum; ESR (Equivalent Series Resistance): 4.000 Ohm; SCDType: spec
footprint CAPMP3216X180N (Capacitor, polarized, Molded Body, EIA 535BAAC size A; 3.20mm L X 1.60mm W X 1.80mm H)
pins: 1, 2

## CAPT_100u_1210_6V3
designator C?, comment Ratings: 6V3  (hidden comment: 100µ)
Capacitor SMD Tantalum 100uF 20% 6.3V 1210; Manufacturer 1: AVX Corporation; Manufacturer Part Number 1: TCJB107M006R0045; SCDType: spec
footprint CAPMP3528X210N (Molded body capacitor, Body 3.5x2.8mm, 1210, IPC Nominal settings)
pins: 1, 2

## CAPT_330u_2917_6V3
designator C?, comment 330µ
Capacitor SMD Tant 330uF 20% 6V3 2917; Manufacturer Size Code: D; Manufacturer Part Number: T520D337M006ATE015; Ratings: 6.3V; Material: Solid Tantalum; ESR (Equivalent Series Resistance): 15 mOhm; SCDType: spec
footprint CAPMP7343X310N (Molded body capacitor, Body 7.3x4.3mm, 2917, IPC Nominal settings)
pins: 1, 2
